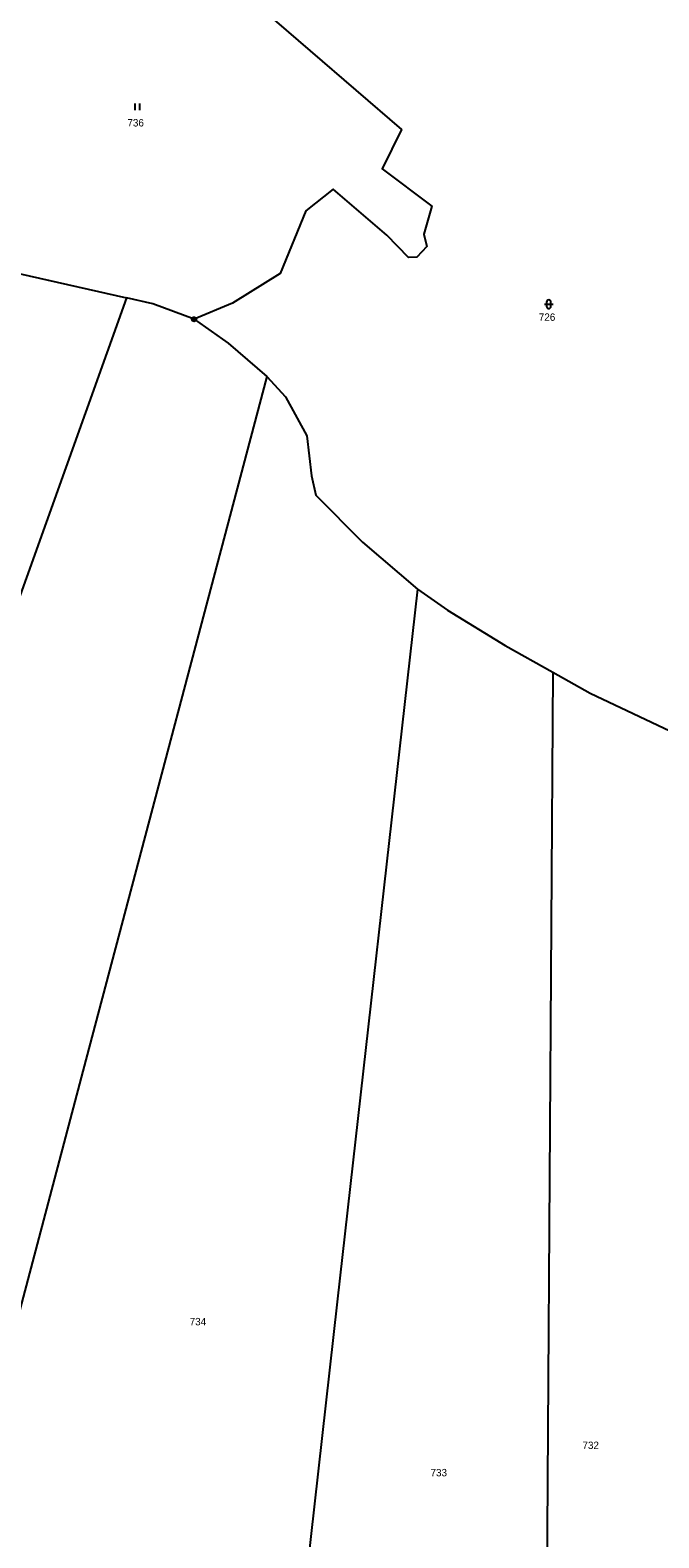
# Model space of a CAD drawing. Extents: x -754445 to -751443, y -1030748 to -1028224.
# Drawn here: x -752596.3 to -752451.7, y -1030004.6 to -1029657.7 of the extents above; entities that cross this region are included whole.
import ezdxf
from ezdxf.enums import TextEntityAlignment as Align

# ---------------------------------------------------------------- set-up
doc = ezdxf.new("R2010")
doc.units = 0
doc.header["$LTSCALE"] = 0.68
for name, color, linetype, lineweight in [('1', 7, 'Continuous', 25), ('3', 7, 'Continuous', 25), ('8', 7, 'Continuous', 25)]:
    doc.layers.add(name, color=color, linetype=linetype, lineweight=lineweight)
doc.layers.add('2', color=7, linetype='Continuous')

msp = doc.modelspace()

# ---------------------------------------------------------------- linework, layer by layer
at = {"layer": '1'}
for points in [[(-752542.39, -1029653.41), (-752510.87, -1029680.53), (-752515.35, -1029689.62), (-752503.93, -1029698.14), (-752505.7, -1029704.62), (-752505.05, -1029707.48), (-752507.33, -1029709.9), (-752509.23, -1029709.97), (-752514.25, -1029704.84), (-752526.59, -1029694.24), (-752532.85, -1029699.27), (-752538.82, -1029713.67), (-752549.78, -1029720.51), (-752558.62, -1029724.21)], [(-752623.57, -1029720.38), (-752610.17, -1029711.13), (-752574.18, -1029719.27)], [(-752574.18, -1029719.27), (-752625.19, -1029861.7), (-752676.19, -1030004.13)], [(-752558.62, -1029724.21), (-752568.11, -1029720.64), (-752574.18, -1029719.27)], [(-752558.62, -1029724.21), (-752550.78, -1029729.67), (-752541.89, -1029737.4)], [(-752541.89, -1029737.4), (-752583.5, -1029894.61), (-752625.1, -1030051.81)], [(-752541.89, -1029737.4), (-752537.57, -1029742.09), (-752532.65, -1029751), (-752531.61, -1029760.23), (-752530.6, -1029764.66), (-752519.82, -1029775.49), (-752507.16, -1029786.29)], [(-752507.16, -1029786.29), (-752525.64, -1029950.35), (-752544.12, -1030114.41)], [(-752507.16, -1029786.29), (-752500.26, -1029791.17), (-752487.04, -1029799.25), (-752476.09, -1029805.42)], [(-752476.09, -1029805.42), (-752477.23, -1029979.89), (-752478.36, -1030154.36)], [(-752476.09, -1029805.42), (-752467.49, -1029810.27), (-752447.71, -1029819.58)]]:
    msp.add_lwpolyline(points, dxfattribs=at)
at = {"layer": '3'}
for p, q in [((-752572.121, -1029676.08), (-752572.121, -1029674.58)), ((-752571.12, -1029676.08), (-752571.12, -1029674.58)), ((-752478.001, -1029720.741), (-752475.999, -1029720.741)), ((-752477.501, -1029720.241), (-752477.501, -1029721.242)), ((-752476.499, -1029721.242), (-752476.499, -1029720.241))]:
    msp.add_line(p, q, dxfattribs=at)
for centre, start, end in [((-752477, -1029720.2409), 0, 180), ((-752477, -1029721.2409), 180, 359.98789)]:
    msp.add_arc(centre, 0.5, start, end, dxfattribs=at)
at = {"layer": '8'}
for radius in [0.5, 0.0303]:
    msp.add_circle((-752558.62, -1029724.2099), radius, dxfattribs=at)

# ---------------------------------------------------------------- texts
at = {"layer": '2'}
for s, p in [('736', (-752572.049, -1029679.836)), ('726', (-752477.379, -1029724.556)), ('734', (-752557.719, -1029955.726)), ('732', (-752467.339, -1029984.186)), ('733', (-752502.299, -1029990.476))]:
    msp.add_text(s, height=1.7, dxfattribs=at).set_placement(p, align=Align.CENTER)

doc.saveas('drawing.dxf')
